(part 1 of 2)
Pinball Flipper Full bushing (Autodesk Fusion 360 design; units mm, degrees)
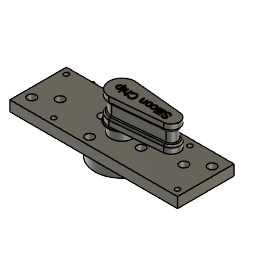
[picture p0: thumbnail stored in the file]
sketch "Flipper" plane through (0, 0, 0) normal (0, 0, 1) x axis (1, 0, 0)
  line L1 (47.7564, -7.9642) -> (0, -12.5)
  line L2 (47.766, 7.9632) -> (1.1968, 12.4426)
  line L3 (-3.0757, 6.1628) -> (6.875, 0.4178)
  line L4 (-6.875, -0.4178) -> (3.0757, -6.1628)
  line L5 (47.7564, 192.0358) -> (0, 187.5)
  line L6 (-6.875, 199.5822) -> (3.0757, 193.8372)
  line L7 (47.766, 207.9632) -> (1.1968, 212.4426)
  line L8 (-3.0757, 206.1628) -> (6.875, 200.4178)
  arc A1 centre (0, 0) radius 12.5 clockwise from (2.3532, -12.2765) to (1.1968, 12.4426)
  arc A2 centre (47, 0) radius 8 clockwise from (47.766, 7.9632) to (47.7564, -7.9642)
  circle C1 centre (0, 0) radius 6.8
  circle C2 centre (3.7239, -2.15) radius 1.4
  circle C3 centre (-3.7239, 2.15) radius 1.4
  arc A3 centre (47, 200) radius 8 clockwise from (47.766, 207.9632) to (47.7564, 192.0358)
  circle C4 centre (-3.7239, 202.15) radius 1.4
  circle C5 centre (0, 200) radius 6.8
  arc A4 centre (0, 200) radius 12.5 clockwise from (2.3532, 187.7235) to (1.1968, 212.4426)
  circle C6 centre (3.7239, 197.85) radius 1.4
  point P1 (0, 0)
  point P2 (0, 0)
  point P4 (0, -12.5)
  point P8 (2.3532, -12.2765)
  point P9 (0, 0)
  point P26 (0, 187.5)
  point P23 (2.3532, 187.7235)
  point P3 (47, 0)
  coincident P1 P2
  coincident P4 A1
  tangent L1 A2
  tangent L2 A1
  tangent L2 A2
  coincident L1 P8
  coincident P1 P9
  coincident P26 A4
  tangent L5 A3
  tangent L7 A4
  tangent A3 L7
  coincident P23 L5
  dimension "d6" diameter C1 = 13.6
  dimension "d174" diameter P3 = 4
  dimension "d363" diameter C2 = 2.8
  dimension "d364" diameter C3 = 2.8
  dimension "d578" diameter C5 = 13.6
  dimension "d579" diameter C6 = 2.8
  dimension "d580" diameter C4 = 2.8
sketch "Bushing" plane through (0, 0, 0) normal (0, 0, 1) x axis (1, 0, 0)
  circle C1 centre (0, 0) radius 7.3
  circle C2 centre (0, 0) radius 11
  circle C3 centre (0, 200) radius 7.3
  circle C4 centre (0, 200) radius 11
  point P1 (0, 0)
  point P2 (0, 0)
  point P3 (0, 0)
  coincident P1 P2
  coincident P1 P3
extrude "Extrude1" new body sketch "Flipper" profile of A1 A2 L1 L2 C1 L4 L3 C2 C3 blind 25 from offset 0.7 bodies "DO NOT USE FLIPPER PROTO"
extrude "Extrude2" add sketch "Flipper" profile of C1 L4 L3 C2 C3 against normal blind 30.8 and along normal blind 0.7
sketch "Washers Upper" plane through (0, 0, 0) normal (0, 0, 1) x axis (1, 0, 0)
  circle C1 centre (0, 0) radius 13.5
  circle C2 centre (0, 0) radius 7.3
  circle C3 centre (0, 200) radius 13.5
  circle C4 centre (0, 200) radius 7.3
  point P1 (0, 0)
  point P2 (0, 0)
  point P3 (0, 0)
  coincident P1 P2
  coincident P1 P3
  dimension "d368" diameter C1 = 27
  dimension "d581" diameter C3 = 27
extrude "Extrude3" new body sketch "Washers Upper" profile of C1 C2 blind -0.8 from offset 0.4 bodies "Washer Upper"
extrude "Extrude4" new body sketch "Bushing" profile of C1 C2 blind -29 from offset -10.2 bodies "Base and Bushing 9mm deck"
sketch "Deck Section" plane through (0, 0, 0) normal (0, 0, 1) x axis (1, 0, 0)
  line L1 (-50, 50) -> (-50, 0)
  line L2 (50, 50) -> (-50, 50)
  line L3 (50, -50) -> (50, 50)
  line L4 (-50, -50) -> (50, -50)
  line L5 (-50, 0) -> (-50, -50)
  circle C1 centre (0, 0) radius 11.5
  point P1 (0, 0)
  point P2 (0, 0)
  coincident P1 P2
  vertical L1
  perpendicular L1 L2
  perpendicular L2 L3
  perpendicular L3 L4
  perpendicular L2 L5
extrude "Extrude5" new body sketch "Deck Section" blind -9 from offset -1.2 bodies "Base Section"
sketch "Solenoid Assembly" plane through (0, 0, -10.2) normal (0, 0, -1) x axis (1, 0, 0)
  line L1 (25, -25) -> (25, 25)
  line L2 (-100, -25) -> (25, -25)
  line L3 (-100, 25) -> (-100, -25)
  line L4 (25, 25) -> (-100, 25)
  line L5 (-100, 225) -> (-100, 175)
  line L6 (25, 175) -> (25, 225)
  line L7 (-100, 175) -> (25, 175)
  line L8 (25, 225) -> (-100, 225)
  circle C1 centre (0, 0) radius 11.5
  circle C2 centre (0, 0) radius 7.3
  circle C3 centre (0, 200) radius 7.3
  point P1 (0, 0)
  point P3 (0, 0)
  coincident P1 P3
  vertical L1
  perpendicular L2 L3
  perpendicular L1 L4
  vertical L6
  perpendicular L5 L7
  perpendicular L6 L8
sketch "Solenoid 22mm" plane through (0, 0, 0) normal (0, 0, 1) x axis (1, 0, 0)
  line L1 (-11, 0) -> (-11, -26)
  line L2 (11, -26) -> (11, 0)
  line L3 (-11, -26) -> (11, -26)
  line L4 (11, 0) -> (-11, 0)
  circle C1 centre (6, -5) radius 1.8
  circle C2 centre (-6, -20) radius 1.8
  point P2 (11, -26)
  point P3 (11, -26)
  point P4 (11, -26)
  coincident P2 P3
  horizontal L3
  perpendicular L1 L3
  perpendicular L1 L4
  coincident P2 P4
  perpendicular L2 L3
sketch "Solenoid 37mm" plane through (0, 0, 0) normal (0, 0, 1) x axis (1, 0, 0)
  line L1 (-2.5, -5.5015) -> (-2.506, -11.3658)
  line L2 (-11, 0) -> (-11, -37)
  line L3 (-5.5, -5.5015) -> (-5.494, -11.3656)
  line L4 (-11, 0) -> (11, 0)
  line L5 (2.5, -31.4995) -> (2.5022, -25.4191)
  line L6 (-2.5, -25.5008) -> (-2.503, -31.4046)
  line L7 (5.5, -25.5) -> (5.5, -31.5)
  line L8 (11, 0) -> (11, -37)
  line L9 (-5.5, -25.5) -> (-5.5, -31.5)
  line L10 (-11, -37) -> (11, -37)
  line L11 (2.5, -5.5015) -> (2.506, -11.3658)
  line L12 (-11, 0) -> (-11, -37)
  line L13 (-11, 0) -> (11, 0)
  line L14 (11, 0) -> (11, -37)
  line L15 (5.5, -5.5015) -> (5.494, -11.3656)
  line L16 (-11, -37) -> (11, -37)
  line L17 (-11, 0) -> (-11, -37)
  line L18 (-11, 0) -> (11, 0)
  line L19 (2.5, -31.4995) -> (2.5021, -25.5799)
  line L20 (5.5, -25.5) -> (5.5, -31.5)
  line L21 (11, 0) -> (11, -37)
  line L22 (-11, -37) -> (11, -37)
  circle C1 centre (4, -28.5) radius 1.5
  arc A1 centre (-4, -31.5) radius 1.5 clockwise from (-2.503, -31.4046) to (-5.5, -31.5)
  arc A2 centre (-4, -25.5) radius 1.5 clockwise from (-5.5, -25.5) to (-2.5, -25.5008)
  arc A3 centre (-4, -11.5) radius 1.5 clockwise from (-2.506, -11.3658) to (-5.494, -11.3656)
  arc A4 centre (4, -11.5) radius 1.5 clockwise from (5.4939, -11.365) to (2.5061, -11.365)
  circle C2 centre (-4, -28.5) radius 1.5
  arc A5 centre (4, -31.5) radius 1.5 clockwise from (5.5, -31.5) to (2.5, -31.4995)
  arc A6 centre (4, -25.5) radius 1.5 clockwise from (2.5022, -25.4191) to (5.5, -25.5)
  arc A7 centre (-4, -5.5) radius 1.5 clockwise from (-5.5, -5.5015) to (-2.5, -5.5015)
  circle C3 centre (-4, -8.5) radius 1.5
  circle C4 centre (4, -8.5) radius 1.5
  circle C5 centre (4, -28.5) radius 1.5
  arc A8 centre (-4, -31.5) radius 1.5 clockwise from (-2.503, -31.4045) to (-5.5, -31.5)
  arc A9 centre (4, -5.5) radius 1.5 clockwise from (2.5, -5.5015) to (5.5, -5.5015)
  arc A10 centre (-4, -11.5) radius 1.5 clockwise from (-2.5061, -11.365) to (-5.4939, -11.365)
  arc A11 centre (4, -11.5) radius 1.5 clockwise from (5.494, -11.3656) to (2.506, -11.3658)
  circle C6 centre (-4, -28.5) radius 1.5
  arc A12 centre (4, -31.5) radius 1.5 clockwise from (5.5, -31.5) to (2.5, -31.4995)
  circle C7 centre (-4, -8.5) radius 1.5
  circle C8 centre (4, -8.5) radius 1.5
  circle C9 centre (4, -28.5) radius 1.5
  arc A13 centre (-4, -31.5) radius 1.5 clockwise from (-2.503, -31.4045) to (-5.5, -31.5)
  arc A14 centre (-4, -11.5) radius 1.5 clockwise from (-2.5061, -11.365) to (-5.4939, -11.365)
  arc A15 centre (4, -11.5) radius 1.5 clockwise from (5.4939, -11.365) to (2.5061, -11.365)
  circle C10 centre (-4, -28.5) radius 1.5
  arc A16 centre (4, -31.5) radius 1.5 clockwise from (5.5, -31.5) to (2.5, -31.4995)
  arc A17 centre (4, -25.5) radius 1.5 clockwise from (2.5021, -25.5799) to (5.5, -25.5)
  circle C11 centre (-4, -8.5) radius 1.5
  circle C12 centre (4, -8.5) radius 1.5
  point P28 (2.5, -31.4995)
  point P7 (2.5, -31.4995)
  point P83 (2.5, -31.4995)
  point P67 (2.5, -31.4995)
  tangent L1 A7
  tangent L3 A7
  tangent A2 L6
  tangent A6 L7
  coincident P28 A5
  tangent A5 L5
  tangent A2 L9
  coincident P7 L5
  tangent A9 L15
  tangent L11 A9
  tangent A17 L20
  coincident P83 A16
  tangent A16 L19
  coincident P67 L19
extrude "Extrude6" new body sketch "Solenoid 22mm" along normal blind 25 bodies "Solenoid 22mm"
extrude "Extrude7" new body sketch "Solenoid 37mm" along normal blind 26 bodies "Solenoid 37mm"
sketch "Solenoid 37mm Plunger" plane through (0, -37, 0) normal (0, -1, 0) x axis (1, 0, 0)
  line L1 (11, 0) -> (-11, 0)
  line L2 (11, 26) -> (11, 0)
  line L3 (-11, 26) -> (11, 26)
  line L4 (-11, 0) -> (-11, 26)
  circle C1 centre (0, 12.5) radius 4
extrude "Extrude8" add sketch "Solenoid 37mm Plunger" profile of C1 along normal blind 23
sketch "Solenoid 22mm Plunger" plane through (0, -26, 0) normal (0, -1, 0) x axis (1, 0, 0)
  line L1 (11, 0) -> (-11, 0)
  line L2 (11, 25) -> (11, 0)
  line L3 (-11, 25) -> (11, 25)
  line L4 (-11, 0) -> (-11, 25)
  circle C1 centre (0, 12.5) radius 4
extrude "Extrude9" add sketch "Solenoid 22mm Plunger" profile of C1 along normal blind 20
sketch "Washer Lower TBA" plane through (0, 0, -10.2) normal (0, 0, -1) x axis (1, 0, 0)
  circle C1 centre (0, 0) radius 15
  circle C2 centre (0, 0) radius 11.5
  circle C3 centre (0, 200) radius 15
  circle C4 centre (0, 200) radius 11.5
  dimension "d38" diameter C1 = 30
  dimension "d582" diameter C3 = 30
move_face "MoveFace1"
extrude "Extrude11" cut sketch "Flipper" profile of C1 L4 L3 blind -19 taper 3 from offset -22.3
sketch "Flipper Drive" plane through (0, 0, -10.2) normal (0, 0, -1) x axis (1, 0, 0)
  line L1 (-0.123, 7.0989) -> (-6.7129, -2.3124)
  line L2 (6.7129, 2.3124) -> (0.123, -7.0989)
  line L3 (-12.2873, 8.6036) -> (0, 0)
  line L4 (-3.5311, 12.3916) -> (-8.1915, 5.7358)
  line L5 (9.4727, 26.0261) -> (0, 0)
  line L6 (25.5365, 11.9079) -> (0, 0)
  line L7 (-11.1615, -30.666) -> (0, 0)
  line L8 (30.0891, 14.0308) -> (0, 0)
  line L9 (-3.473, 19.6962) -> (0, 0)
  line L10 (23.9139, 11.1513) -> (0, 0)
  line L11 (-12.8558, 15.3209) -> (0, 0)
  line L12 (25.7028, 11.9854) -> (0, 0)
  line L13 (0, 0) -> (3.473, -19.6962)
  line L14 (0, 0) -> (12.8558, -15.3209)
  line L15 (25.4979, -9.2805) -> (0, 0)
  line L16 (24.592, 11.4674) -> (0, 0)
  line L17 (0, 0) -> (-25.4979, 9.2805)
  line L18 (23.8505, 4.2055) -> (0, 0)
  line L19 (21.9493, 10.2351) -> (0, 0)
  line L20 (0, 0) -> (-24.5999, 0)
  line L21 (19.205, 16.1149) -> (0, 0)
  line L22 (21.4291, 9.9926) -> (0, 0)
  line L23 (0, 0) -> (-15.3639, -18.31)
  line L24 (-20.1737, -24.0421) -> (0, 0)
  line L25 (28.4442, 13.2638) -> (0, 0)
  line L26 (-28.4796, 0) -> (0, 0)
  line L27 (25.8113, 12.036) -> (0, 0)
  line L28 (30.112, 5.3096) -> (23.8505, 4.2055)
  line L29 (25.0112, 20.9869) -> (19.205, 16.1149)
  line L30 (2.8887, 206.4858) -> (-7.0612, 200.7412)
  line L31 (0, 200) -> (5.1764, 180.6815)
  line L32 (29.5346, 192.0862) -> (23.3932, 193.7318)
  line L33 (28.4796, 200) -> (0, 200)
  line L34 (-23.0757, 176.9243) -> (0, 200)
  line L35 (26.3861, 200) -> (0, 200)
  line L36 (33.1997, 200) -> (0, 200)
  line L37 (31.5373, 208.4504) -> (24.2161, 206.4887)
  line L38 (27.1343, 200) -> (0, 200)
  line L39 (24.2184, 200) -> (0, 200)
  line L40 (-7.5, 212.9904) -> (0, 200)
  line L41 (7.0612, 199.2588) -> (-2.8887, 193.5142)
  line L42 (0, 200) -> (-5.1764, 180.6815)
  line L43 (23.6444, 200) -> (0, 200)
  line L44 (0, 200) -> (-21.6626, 189.8986)
  line L45 (-28.4442, 186.7362) -> (0, 200)
  line L46 (0, 200) -> (-22.295, 210.3963)
  line L47 (19.5843, 219.5843) -> (0, 200)
  line L48 (0, 200) -> (-19.1868, 219.1868)
  line L49 (24.2161, 206.4887) -> (0, 200)
  line L50 (28.1764, 200) -> (0, 200)
  line L51 (-25.8113, 212.036) -> (0, 200)
  line L52 (23.3932, 193.7318) -> (0, 200)
  line L53 (28.3599, 200) -> (0, 200)
  line L54 (-5.1764, 219.3185) -> (0, 200)
  line L55 (2.0367, 212.7229) -> (-5, 208.6603)
  line L56 (5.1764, 219.3185) -> (0, 200)
  line L57 (19.1868, 180.8132) -> (0, 200)
  line L58 (31.3847, 200) -> (0, 200)
  line L59 (14.274, 17.0132) -> (0, 0)
  line L60 (22.8697, 27.2586) -> (14.274, 17.0132)
  line L61 (22.194, 0.0202) -> (0, 0)
  line L62 (30.71, 0.0279) -> (22.194, 0.0202)
  line L63 (-0.123, 7.0989) -> (-6.7129, -2.3124)
  line L64 (6.7129, 2.3124) -> (0.123, -7.0989)
  line L65 (2.8887, 6.4858) -> (-7.0612, 0.7412)
  line L66 (7.0612, -0.7412) -> (-2.8887, -6.4858)
  arc A1 centre (0, 0) radius 7.1 clockwise from (0.123, -7.0989) to (-6.7129, -2.3124)
  arc A2 centre (0, 0) radius 7.1 clockwise from (-0.123, 7.0989) to (6.7129, 2.3124)
  circle C1 centre (0, 0) radius 15
  arc A3 centre (0, 0) radius 7.1 clockwise from (-6.7129, -2.3124) to (-0.123, 7.0989)
  arc A4 centre (0, 0) radius 7.1 clockwise from (6.7129, 2.3124) to (0.123, -7.0989)
  arc A5 centre (0, 0) radius 20 clockwise from (-12.8558, 15.3209) to (-3.473, 19.6962)
  arc A6 centre (0, 0) radius 20 clockwise from (12.8558, -15.3209) to (3.473, -19.6962)
  arc A7 centre (0, 0) radius 16 clockwise from (5.4723, 15.0351) to (12.2567, 10.2846)
  arc A8 centre (0, 0) radius 16 clockwise from (15.7569, 2.7784) to (15.0351, -5.4723)
  arc A9 centre (0, 0) radius 16 clockwise from (-5.4723, -15.0351) to (-10.2846, -12.2567)
  arc A10 centre (0, 0) radius 16 clockwise from (-16, 0) to (-15.0351, 5.4723)
  arc A11 centre (0, 0) radius 16 clockwise from (12.2567, 10.2846) to (15.7569, 2.7784)
  arc A12 centre (0, 0) radius 16 clockwise from (-10.2846, -12.2567) to (-16, 0)
  arc A13 centre (0, 0) radius 21 clockwise from (-13.4985, -16.0869) to (-21, 0)
  arc A14 centre (0, 0) radius 26 clockwise from (8.8925, 24.432) to (24.432, -8.8925)
  arc A15 centre (0, 0) radius 26 clockwise from (-8.8925, -24.432) to (-16.7125, -19.9172)
  arc A16 centre (0, 0) radius 26 clockwise from (-26, 0) to (-24.432, 8.8925)
  arc A17 centre (0, 0) radius 26 clockwise from (24.432, -8.8925) to (-8.8925, -24.432)
  arc A18 centre (0, 0) radius 21 clockwise from (-19.7335, 7.1824) to (7.1824, 19.7335)
  arc A19 centre (0, 0) radius 26 clockwise from (-24.432, 8.8925) to (8.8925, 24.432)
  arc A20 centre (0, 0) radius 21 clockwise from (19.7335, -7.1824) to (-7.1824, -19.7335)
  circle C2 centre (-11.3357, -19.6167) radius 1.75
  circle C3 centre (-11.3357, -19.6167) radius 4
  circle C4 centre (-22.3238, 3.9473) radius 1.75
  circle C5 centre (-22.3238, 3.9473) radius 4
  circle C6 centre (11.2096, 19.5842) radius 1.75
  circle C7 centre (11.2096, 19.5842) radius 4
  circle C8 centre (22.1977, -3.9798) radius 1.75
  circle C9 centre (22.1977, -3.9798) radius 4
  arc A21 centre (0, 0) radius 26 clockwise from (-16.7125, -19.9172) to (-26, 0)
  arc A22 centre (0, 200) radius 20 clockwise from (5.1764, 180.6815) to (-5.1764, 180.6815)
  arc A23 centre (0, 200) radius 26 clockwise from (18.3848, 218.3848) to (18.3848, 181.6152)
  circle C10 centre (18.436, 187.0119) radius 4
  arc A24 centre (0, 200) radius 26 clockwise from (-18.3848, 218.3848) to (18.3848, 218.3848)
  arc A25 centre (0, 200) radius 26 clockwise from (18.3848, 181.6152) to (-18.3848, 181.6152)
  arc A26 centre (0, 200) radius 21 clockwise from (-14.8492, 214.8492) to (14.8492, 214.8492)
  circle C11 centre (0, 200) radius 15
  arc A27 centre (0, 200) radius 16 clockwise from (15.4548, 195.8589) to (11.3137, 188.6863)
  arc A28 centre (0, 200) radius 16 clockwise from (-14.5009, 206.7619) to (-11.3137, 211.3137)
  arc A29 centre (0, 200) radius 16 clockwise from (-11.3137, 188.6863) to (-14.5009, 193.2381)
  arc A30 centre (0, 200) radius 16 clockwise from (15.4548, 204.1411) to (15.4548, 195.8589)
  arc A31 centre (0, 200) radius 21 clockwise from (14.8492, 185.1508) to (-14.8492, 185.1508)
  circle C12 centre (18.436, 213.0119) radius 4
  circle C13 centre (18.436, 213.0119) radius 1.75
  arc A32 centre (0, 200) radius 26 clockwise from (-18.3848, 181.6152) to (-23.564, 189.0119)
  arc A33 centre (0, 200) radius 26 clockwise from (-23.564, 210.9881) to (-18.3848, 218.3848)
  circle C14 centre (-18.564, 187.0119) radius 1.75
  circle C15 centre (-18.564, 187.0119) radius 4
  arc A34 centre (0, 200) radius 7.1 clockwise from (-7.0612, 200.7412) to (2.8887, 206.4858)
  circle C16 centre (-18.564, 213.0119) radius 4
  arc A35 centre (0, 200) radius 7.1 clockwise from (7.0612, 199.2588) to (-2.8887, 193.5142)
  arc A36 centre (0, 200) radius 16 clockwise from (-14.5009, 193.2381) to (-14.5009, 206.7619)
  circle C17 centre (-18.564, 213.0119) radius 1.75
  arc A37 centre (0, 200) radius 7.1 clockwise from (-2.8887, 193.5142) to (-7.0612, 200.7412)
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  point P1 (0, 0)
  point P2 (0, 0)
  point P3 (6.7129, 2.3124)
  point P8 (0, 0)
  point P12 (-12.2873, 8.6036)
  point P7 (0, 0)
  point P15 (0, 0)
  point P14 (0, 0)
  point P18 (0, 0)
  point P11 (0, 0)
  point P21 (0, 0)
  point P23 (0, 0)
  point P26 (0, 0)
  point P27 (0, 0)
  point P30 (0, 0)
  point P33 (0, 0)
  point P38 (0, 0)
  point P43 (0, 0)
  point P49 (12.2567, 10.2846)
  point P50 (5.4723, 15.0351)
  point P48 (0, 0)
  point P53 (15.7569, 2.7784)
  point P36 (0, 0)
  point P51 (0, 0)
  point P55 (-10.2846, -12.2567)
  point P54 (0, 0)
  point P57 (-13.4985, -16.0869)
  point P58 (-21, 0)
  point P61 (-16, 0)
  point P60 (-15.0351, 5.4723)
  point P59 (0, 0)
  point P62 (0, 0)
  point P46 (-15.3639, -18.31)
  point P65 (0, 0)
  point P41 (-24.5999, 0)
  point P68 (0, 0)
  point P13 (0, 0)
  point P71 (0, 0)
  point P75 (8.8925, 24.432)
  point P77 (-16.7125, -19.9172)
  point P76 (0, 0)
  point P81 (-26, 0)
  point P79 (0, 0)
  point P82 (0, 0)
  point P85 (-19.7335, 7.1824)
  point P83 (0, 0)
  point P86 (0, 0)
  point P88 (-7.1824, -19.7335)
  point P73 (0, 0)
  point P87 (0, 0)
  point P42 (0, 0)
  point P98 (0, 0)
  point P129 (7.0612, 199.2588)
  point P128 (0, 200)
  point P135 (0, 200)
  point P117 (-7.5, 212.9904)
  point P133 (0, 200)
  point P137 (0, 200)
  point P112 (0, 200)
  point P140 (0, 200)
  point P118 (0, 200)
  point P155 (0, 200)
  point P171 (0, 200)
  point P177 (0, 200)
  point P178 (0, 200)
  point P182 (0, 200)
  point P174 (0, 200)
  point P125 (0, 200)
  point P163 (0, 200)
  point P161 (15.4548, 204.1411)
  point P162 (11.3137, 211.3137)
  point P166 (0, 200)
  point P151 (15.4548, 195.8589)
  point P153 (0, 200)
  point P183 (0, 200)
  point P194 (-14.5009, 193.2381)
  point P191 (-19.0325, 191.125)
  point P192 (-19.0325, 208.875)
  point P176 (-14.5009, 206.7619)
  point P175 (-11.3137, 211.3137)
  point P193 (0, 200)
  point P165 (-21.6626, 189.8986)
  point P185 (0, 200)
  point P168 (-22.295, 210.3963)
  point P109 (0, 200)
  point P113 (0, 200)
  point P121 (0, 200)
  point P105 (18.3848, 218.3848)
  point P144 (-23.564, 189.0119)
  point P99 (0, 200)
  point P148 (-23.564, 210.9881)
  point P147 (0, 200)
  point P190 (0, 200)
  point P149 (0, 200)
  point P146 (-14.8492, 214.8492)
  point P143 (0, 200)
  point P106 (0, 200)
  point P123 (-14.8492, 185.1508)
  point P111 (0, 200)
  point P124 (0, 200)
  point P110 (0, 200)
  point P157 (0, 200)
  point P196 (0, 0)
  point P197 (20.9994, -0.1635)
  point P198 (13.3537, 16.2074)
  point P199 (0, 0)
  point P200 (14.274, 17.0132)
  point P202 (0, 0)
  point P203 (22.194, 0.0202)
  point P205 (0, 0)
  point P207 (-18.7939, 6.8404)
  point P206 (0, 0)
  point P209 (18.7939, -6.8404)
  point P208 (0, 0)
  coincident P1 P2
  coincident P3 A1
  coincident P2 P8
  concentric A1 C1
  coincident C1 P12
  coincident P7 P15
  coincident P14 P18
  coincident P11 P21
  coincident P2 P23
  coincident P26 P27
  coincident P27 P30
  coincident P7 P33
  coincident P11 P38
  coincident P2 P43
  coincident L21 P49
  coincident L5 P50
  coincident P14 P48
  coincident L18 P53
  coincident P36 P51
  coincident L23 P55
  coincident P1 P54
  coincident L23 P57
  coincident L20 P58
  coincident L20 P61
  coincident L17 P60
  coincident P27 P59
  coincident P1 P62
  coincident P46 L24
  parallel L23 L24
  coincident P7 P65
  coincident P41 L26
  parallel L20 L26
  coincident P51 P68
  parallel L18 L28
  parallel L21 L29
  coincident P13 P71
  coincident L5 P75
  coincident L24 P77
  coincident P13 P76
  coincident L26 P81
  coincident P54 P79
  coincident P54 P82
  coincident L17 P85
  coincident P82 P83
  coincident P59 P86
  coincident L7 P88
  coincident P73 P87
  concentric C2 C3
  concentric C4 C5
  concentric C8 C9
  concentric C6 C7
  coincident P42 P98
  coincident P129 A37
  coincident P128 P135
  concentric C11 A37
  coincident P117 C11
  horizontal L50
  coincident P133 P137
  horizontal L36
  coincident P112 P140
  horizontal L35
  coincident P118 P155
  horizontal L53
  coincident P128 P171
  coincident P177 P178
  coincident P177 P182
  horizontal L38
  coincident P133 P174
  horizontal L39
  coincident P118 P125
  horizontal L43
  coincident P128 P163
  coincident P161 L49
  coincident P162 L47
  coincident P112 P166
  coincident P151 L52
  coincident P153 P183
  coincident P194 L44
  coincident P191 L44
  coincident P192 L46
  coincident P176 L46
  coincident P175 L48
  coincident P177 P193
  horizontal L58
  coincident P165 L45
  parallel L44 L45
  horizontal L33
  coincident P133 P185
  coincident P168 L51
  parallel L46 L51
  coincident P109 P153
  parallel L32 L52
  parallel L37 L49
  coincident P113 P121
  coincident P105 L47
  coincident P144 L45
  coincident P99 P113
  coincident P148 L51
  coincident P147 P190
  coincident P149 P190
  coincident P146 L48
  coincident P143 P149
  coincident P106 P193
  coincident P123 L34
  coincident P111 P124
  concentric C14 C15
  concentric C16 C17
  concentric C12 C13
  coincident P110 P157
  coincident P14 P196
  coincident C9 P197
  coincident C7 P198
  coincident P11 P199
  coincident C7 P200
  tangent C7 L59
  tangent C7 L60
  coincident P76 P202
  coincident C9 P203
  tangent C9 L61
  tangent C9 L62
  coincident P59 P205
  coincident L17 P207
  coincident P54 P206
  coincident L15 P209
  coincident P14 P208
  dimension "d299" angle L7 L8 = 135
  dimension "d300" angle L9 L10 = 75
  dimension "d301" angle L11 L12 = 105
  dimension "d302" radius A5 = 20
  dimension "d303" radius A6 = 20
  dimension "d307" radius A7 = 16
  dimension "d309" radius A8 = 16
  dimension "d311" radius A9 = 16
  dimension "d314" radius A10 = 16
  dimension "d513" radius A14 = 26
  dimension "d514" radius A15 = 26
  dimension "d515" radius A16 = 26
  dimension "d517" radius A18 = 21
  dimension "d518" radius A20 = 21
  dimension "d520" diameter C2 = 3.5
  dimension "d521" diameter C3 = 8
  dimension "d522" diameter C4 = 3.5
  dimension "d523" diameter C5 = 8
  dimension "d524" diameter C8 = 3.5
  dimension "d525" diameter C9 = 8
  dimension "d526" diameter C6 = 3.5
  dimension "d527" diameter C7 = 8
  dimension "d583" angle L34 L36 = 135
  dimension "d584" angle L35 L56 = 75
  dimension "d585" angle L53 L54 = 105
  dimension "d586" radius = 20
  dimension "d587" radius A22 = 20
  dimension "d588" radius = 16
  dimension "d589" radius A27 = 16
  dimension "d590" radius A29 = 16
  dimension "d591" radius A28 = 16
  dimension "d592" radius A23 = 26
  dimension "d593" radius A32 = 26
  dimension "d594" radius A33 = 26
  dimension "d595" radius A26 = 21
  dimension "d596" radius A31 = 21
  dimension "d597" diameter C14 = 3.5
  dimension "d598" diameter C15 = 8
  dimension "d599" diameter C17 = 3.5
  dimension "d600" diameter C16 = 8
  dimension "d601" diameter = 3.5
  dimension "d602" diameter C10 = 8
  dimension "d603" diameter C13 = 3.5
  dimension "d604" diameter C12 = 8
  dimension "d730" radius = 21
work_plane "WorkPlane1" RotateAngle 90
sketch "Flipper Drive Perpendicular Plane" plane through (0, 0, 0) normal (-0.5736, 0.8192, 0) x axis (-0.8192, -0.5736, 0)
  circle C1 centre (10, -32.2) radius 2
  circle C2 centre (10, -32.2) radius 4.5
  circle C3 centre (-10, -32.2) radius 2
  circle C4 centre (-10, -32.2) radius 4.5
  dimension "d51" diameter C1 = 4
  dimension "d52" diameter C2 = 9
  dimension "d53" diameter C3 = 4
  dimension "d54" diameter C4 = 9
extrude "Extrude12" new body sketch "Flipper Drive" profile of A2 C1 A3 A4 blind 8.8 from offset 11.2 bodies "Flipper Drive"
extrude "Extrude13" add sketch "Flipper Drive" profile of L1 L2 L3 A3 A4 blind 8.8 taper 3 from offset 11.2
sketch "Flipper Drive Top Labelling" plane through (0, 0, -30.2) normal (0, 0, -1) x axis (1, 0, 0)
  line L1 (3.3862, 6.2405) -> (-7.0975, 0.1877)
  line L2 (-3.3862, -6.2405) -> (7.0975, -0.1877)
  curve K1
  curve K2
  curve K3
  curve K4
  curve K5
  curve K6
  curve K7
  curve K8
  line L3 (10, 0) -> (0, 0)
  line L4 (0.4316, 7.0869) -> (-6.5119, -2.8294)
  line L5 (-0.4316, -7.0869) -> (6.5119, 2.8294)
  arc A1 centre (0, 0) radius 7.1 clockwise from (-3.3862, -6.2405) to (-7.0975, 0.1877)
  circle C1 centre (-5, 8.6603) radius 5
  circle C2 centre (-5, 8.6603) radius 3
  circle C3 centre (-5, 8.6603) radius 1.75
  arc A2 centre (0, 0) radius 7.1 clockwise from (3.3862, 6.2405) to (7.0975, -0.1877)
  circle C4 centre (0, 0) radius 15
  arc A3 centre (0, 0) radius 7.1 clockwise from (-0.4316, -7.0869) to (-6.5119, -2.8294)
  arc A4 centre (0, 0) radius 7.1 clockwise from (0.4316, 7.0869) to (6.5119, 2.8294)
  circle C5 centre (0, 0) radius 15
  circle C6 centre (5, -8.6603) radius 1.75
  circle C7 centre (5, -8.6603) radius 3
  circle C8 centre (5, -8.6603) radius 5
  point P1 (0, 0)
  point P8 (0, 0)
  horizontal L3
  coincident P1 P8
  concentric C1 C2
  concentric C1 C3
  concentric C7 C8
  concentric C6 C8
  dimension "d75" Text1-Height = 5
  dimension "d77" Text2-Height = 3
extrude "Extrude20" cut sketch "Flipper Drive Top Labelling" against normal blind 0.6
sketch "Flipper Drive Lower Assembly" plane through (0, 0, -10.2) normal (0, 0, -1) x axis (1, 0, 0)
  line L1 (40.6874, -6.549) -> (14.7287, 38.4892)
  line L2 (-113.7703, -35.5739) -> (14.7287, 38.4892)
  line L3 (-87.8117, -80.6121) -> (12.9793, -22.5191)
  line L4 (40.6874, -6.549) -> (12.9793, -22.5191)
  line L5 (-87.8117, -80.6121) -> (-113.7703, -35.5739)
  line L6 (20.7934, 41.9847) -> (14.7287, 38.4892)
  line L7 (46.7521, -3.0534) -> (40.6874, -6.549)
  line L8 (-94.1551, -30.9647) -> (-102.8153, -35.9647)
  line L9 (-83.4756, -35.9647) -> (-102.8153, -35.9647)
  line L10 (-90.691, -28.9647) -> (-94.1551, -30.9647)
  line L11 (19.0606, 40.986) -> (14.7287, 38.4892)
  circle C1 centre (0, 0) radius 11
  circle C2 centre (-82.8153, -70.6057) radius 2.25
  circle C3 centre (-102.8153, -35.9647) radius 2.25
  circle C4 centre (12.3745, 30.5207) radius 2.25
  circle C5 centre (32.3745, -4.1204) radius 2.25
  point P1 (0, 0)
  point P2 (0, 0)
  point P9 (-102.8153, -35.9647)
  point P14 (-102.8153, -35.9647)
  point P15 (-94.1551, -30.9647)
  point P17 (-90.691, -28.9647)
  point P3 (14.7287, 38.4892)
  point P18 (19.0606, 40.986)
  coincident P1 P2
  perpendicular L1 L2
  perpendicular L1 L4
  perpendicular L3 L5
  perpendicular L1 L6
  perpendicular L1 L7
  horizontal L9
  coincident P9 P14
  parallel L8 L10
  perpendicular L1 L11
  dimension "d132" diameter C2 = 4.5
  dimension "d135" diameter C3 = 4.5
  dimension "d138" diameter C4 = 4.5
  dimension "d139" diameter C5 = 4.5
  dimension "d348" angle L8 L9 = 30
  dimension "d349" distance P14 P15 = 10
  dimension "d357" distance P15 P17 = 4
  dimension "d534" distance P3 P18 = 5
extrude "Extrude21" add sketch "Flipper Drive Lower Assembly" profile of C1 L1 L2 L3 L4 L5 along normal blind 10
sketch "Washer Lower" plane through (0, 0, -20.2) normal (0, 0, -1) x axis (1, 0, 0)
  circle C1 centre (0, 0) radius 7.3
  circle C2 centre (0, 0) radius 7.3
  circle C3 centre (0, 0) radius 13.5
  circle C4 centre (0, 200) radius 13.5
  circle C5 centre (0, 200) radius 7.3
  point P1 (0, 0)
  point P3 (0, 0)
  coincident P1 P3
  dimension "d369" diameter C3 = 27
  dimension "d605" diameter C4 = 27
extrude "Extrude22" new body sketch "Washer Lower" profile of C1 C2 C3 blind 1 from offset 0.2 bodies "Washer Lower"
move "Move1"
move "Move2"
move "Move3"
move "Move4"
work_plane "WorkPlane2" RotateAngle 0
sketch "Construction to Solenoid" plane through (0, 0, -32.2) normal (0, 0, 1) x axis (1, 0, 0)
  line L1 (-83.0796, 37.5009) -> (-8.1915, -5.7358)
  line L2 (85.6995, -5.7358) -> (-8.1915, -5.7358)
  point P2 (-8.1915, -5.7358)
  point P3 (-8.1915, -5.7358)
  horizontal L2
  coincident P2 P3
  dimension "d87" angle L1 L2 = 150
move "Move5"
work_axis "WorkAxis2"
move "Move6"
move "Move7"
work_plane "WorkPlane3" AlongDistance 12.5
work_plane "WorkPlane4" RotateAngle 0
work_plane "WorkPlane5" RotateAngle 0
sketch "Solenoid Coupling" plane through (0, 0, -32.2) normal (0, 0, 1) x axis (1, 0, 0)
  line L1 (14.8548, -15.2705) -> (9.7533, -24.1063)
  line L2 (30.5284, -24.3335) -> (14.8548, -15.2705)
  line L3 (25.433, -33.159) -> (30.5284, -24.3335)
  line L4 (25.433, -33.159) -> (9.7533, -24.1063)
  line L5 (47.3229, -34.0286) -> (34.864, -26.8366)
  line L6 (30.5284, -24.3335) -> (34.864, -26.8366)
  line L7 (34.864, -26.8366) -> (30.629, -34.173)
  line L8 (13.6506, -26.3564) -> (16.6506, -21.1603)
  line L9 (22.6506, -21.1603) -> (16.6506, -21.1603)
  line L10 (13.6506, -26.3564) -> (16.6506, -21.1603)
  line L11 (51.0602, -47.9614) -> (53.55, -46.5429)
  line L12 (51.0602, -47.9614) -> (42.896, -43.2346)
  line L13 (-25.136, -26.8366) -> (-29.3244, -34.0923)
  line L14 (-45.1452, -15.2705) -> (-50.2467, -24.1063)
  line L15 (-34.567, -33.159) -> (-29.4716, -24.3335)
  line L16 (-46.3494, -26.3564) -> (-43.3494, -21.1603)
  line L17 (-8.2143, -48.5931) -> (-5.4963, -46.9921)
  line L18 (-11.811, -34.5286) -> (-25.136, -26.8366)
  line L19 (-29.4716, -24.3335) -> (-25.136, -26.8366)
  line L20 (-29.4716, -24.3335) -> (-45.1452, -15.2705)
  line L21 (-37.3494, -21.1603) -> (-43.3494, -21.1603)
  line L22 (-46.3494, -26.3564) -> (-43.3494, -21.1603)
  line L23 (-10.945, -35.0285) -> (-11.811, -34.5286)
  line L24 (-15.3719, -42.1478) -> (-16.2379, -41.6478)
  line L25 (-89.4716, -24.3335) -> (-105.1452, -15.2705)
  line L26 (-97.3494, -21.1603) -> (-103.3494, -21.1603)
  line L27 (-67.4648, -48.7967) -> (-64.8096, -47.2494)
  line L28 (-106.3494, -26.3564) -> (-103.3494, -21.1603)
  line L29 (-106.3494, -26.3564) -> (-103.3494, -21.1603)
  line L30 (-69.7504, -35.7181) -> (-70.6165, -35.2181)
  line L31 (-70.6165, -35.2181) -> (-85.136, -26.8366)
  line L32 (-74.5059, -42.6477) -> (-75.3719, -42.1477)
  line L33 (-85.136, -26.8366) -> (-89.3244, -34.0922)
  line L34 (-67.4648, -48.7967) -> (-75.3719, -44.2345)
  line L35 (-89.4716, -24.3335) -> (-85.136, -26.8366)
  line L36 (-94.567, -33.159) -> (-89.4716, -24.3335)
  line L37 (-105.1452, -15.2705) -> (-110.2467, -24.1063)
  line L38 (-94.567, -33.159) -> (-110.2467, -24.1063)
  line L39 (-156.3494, -26.3564) -> (-153.3494, -21.1603)
  line L40 (-155.1452, -15.2705) -> (-160.2467, -24.1063)
  line L41 (-147.3494, -21.1603) -> (-153.3494, -21.1603)
  line L42 (-119.2129, -36.0285) -> (-120.0789, -35.5285)
  line L43 (-116.307, -49.4732) -> (-113.7939, -48.0094)
  line L44 (-156.3494, -26.3564) -> (-153.3494, -21.1603)
  line L45 (-144.567, -33.159) -> (-139.4716, -24.3335)
  line L46 (-134.27, -27.3366) -> (-138.4584, -34.5922)
  line L47 (-144.567, -33.159) -> (-160.2467, -24.1063)
  line L48 (-139.4716, -24.3335) -> (-134.27, -27.3366)
  line L49 (-139.4716, -24.3335) -> (-155.1452, -15.2705)
  line L50 (-120.0789, -35.5285) -> (-134.27, -27.3366)
  line L51 (-123.6398, -43.1477) -> (-124.5059, -42.6477)
  line L52 (-116.307, -49.4732) -> (-124.5058, -44.7345)
  line L53 (-204.567, -33.159) -> (-220.2467, -24.1063)
  line L54 (-182.7738, -43.6477) -> (-183.6398, -43.1477)
  line L55 (-207.3494, -21.1603) -> (-213.3494, -21.1603)
  line L56 (-215.1452, -15.2705) -> (-220.2467, -24.1063)
  line L57 (-216.3494, -26.3564) -> (-213.3494, -21.1603)
  line L58 (-216.3494, -26.3564) -> (-213.3494, -21.1603)
  line L59 (-199.4716, -24.3335) -> (-215.1452, -15.2705)
  line L60 (-199.4716, -24.3335) -> (-193.404, -27.8366)
  line L61 (-178.3469, -36.5285) -> (-179.2129, -36.0285)
  line L62 (-179.2129, -36.0285) -> (-193.404, -27.8366)
  line L63 (-175.4401, -49.9688) -> (-183.6398, -45.2345)
  line L64 (-204.567, -33.159) -> (-199.4716, -24.3335)
  line L65 (-175.4401, -49.9688) -> (-172.9348, -48.5134)
  line L66 (-193.404, -27.8366) -> (-197.5924, -35.0922)
  line L67 (-264.567, -33.159) -> (-280.2467, -24.1063)
  line L68 (-275.1452, -15.2705) -> (-280.2467, -24.1063)
  line L69 (-234.5746, -50.467) -> (-232.0726, -49.0156)
  line L70 (-238.3469, -36.5285) -> (-252.538, -28.3366)
  line L71 (-259.4716, -24.3335) -> (-252.538, -28.3366)
  line L72 (-252.538, -28.3366) -> (-256.7263, -35.5922)
  line L73 (-234.5746, -50.467) -> (-242.7738, -45.7345)
  line L74 (-259.4716, -24.3335) -> (-275.1452, -15.2705)
  line L75 (-267.3494, -21.1603) -> (-273.3494, -21.1603)
  line L76 (-276.3494, -26.3564) -> (-273.3494, -21.1603)
  line L77 (-276.3494, -26.3564) -> (-273.3494, -21.1603)
  line L78 (-264.567, -33.159) -> (-259.4716, -24.3335)
  line L79 (25.433, -33.159) -> (42.896, -43.2346)
  line L80 (30.629, -34.173) -> (29.7699, -35.6612)
  line L81 (-30.2298, -35.6615) -> (-29.3244, -34.0923)
  line L82 (-90.23, -35.6618) -> (-75.3719, -44.2345)
  line L83 (-90.23, -35.6618) -> (-89.3244, -34.0922)
  line L84 (-90.23, -35.6618) -> (-94.567, -33.159)
  line L85 (-144.567, -33.159) -> (-124.5058, -44.7345)
  line L86 (-139.3638, -36.1613) -> (-138.4584, -34.5922)
  line L87 (-204.567, -33.159) -> (-183.6398, -45.2345)
  line L88 (-198.4977, -36.6611) -> (-197.5924, -35.0922)
  line L89 (-264.567, -33.159) -> (-242.7738, -45.7345)
  line L90 (-257.6316, -37.161) -> (-256.7263, -35.5922)
  line L91 (-326.2039, -23.3339) -> (-319.2703, -27.337)
  line L92 (-331.2993, -32.1594) -> (-346.979, -23.1067)
  line L93 (-343.0816, -25.3568) -> (-340.0816, -20.1607)
  line L94 (-299.5746, -50.467) -> (-297.0726, -49.0156)
  line L95 (-343.0816, -25.3568) -> (-340.0816, -20.1607)
  line L96 (-334.0816, -20.1607) -> (-340.0816, -20.1607)
  line L97 (-326.2039, -23.3339) -> (-341.8775, -14.2709)
  line L98 (-303.3473, -36.5287) -> (-319.2703, -27.337)
  line L99 (-331.2993, -32.1594) -> (-326.2039, -23.3339)
  line L100 (-319.2703, -27.337) -> (-323.4586, -34.5926)
  line L101 (-299.5746, -50.467) -> (-307.7738, -45.7345)
  line L102 (-331.2993, -32.1594) -> (-307.7738, -45.7345)
  line L103 (-341.8775, -14.2709) -> (-346.979, -23.1067)
  line L104 (-324.3639, -36.1614) -> (-323.4586, -34.5926)
  line L105 (-326.0961, -35.1618) -> (-324.3639, -36.1614)
  line L106 (-393.0316, -31.1598) -> (-367.7738, -45.7345)
  line L107 (-381.0025, -26.3374) -> (-385.1909, -33.593)
  line L108 (-386.0961, -35.1618) -> (-385.1909, -33.593)
  line L109 (-393.0316, -31.1598) -> (-408.7112, -22.1071)
  line L110 (-403.6098, -13.2713) -> (-408.7112, -22.1071)
  line L111 (-387.9362, -22.3343) -> (-403.6098, -13.2713)
  line L112 (-395.8139, -19.1611) -> (-401.8139, -19.1611)
  line L113 (-387.9362, -22.3343) -> (-381.0025, -26.3374)
  line L114 (-393.0316, -31.1598) -> (-387.9362, -22.3343)
  line L115 (-359.5746, -50.467) -> (-367.7738, -45.7345)
  line L116 (-404.8139, -24.3572) -> (-401.8139, -19.1611)
  line L117 (-363.3476, -36.5288) -> (-381.0025, -26.3374)
  line L118 (-404.8139, -24.3572) -> (-401.8139, -19.1611)
  line L119 (-359.5746, -50.467) -> (-357.0726, -49.0156)
  line L120 (-387.8284, -34.1622) -> (-386.0961, -35.1618)
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  point P3 (16.6506, -21.1603)
  point P13 (16.6506, -21.1603)
  point P16 (13.6506, -26.3564)
  point P22 (-43.3494, -21.1603)
  point P33 (-43.3494, -21.1603)
  point P35 (-46.3494, -26.3564)
  point P48 (-103.3494, -21.1603)
  point P55 (-103.3494, -21.1603)
  point P47 (-106.3494, -26.3564)
  point P67 (-153.3494, -21.1603)
  point P78 (-153.3494, -21.1603)
  point P65 (-156.3494, -26.3564)
  point P92 (-213.3494, -21.1603)
  point P94 (-213.3494, -21.1603)
  point P93 (-216.3494, -26.3564)
  point P111 (-273.3494, -21.1603)
  point P115 (-273.3494, -21.1603)
  point P112 (-276.3494, -26.3564)
  point P127 (29.7699, -35.6612)
  point P130 (-139.3638, -36.1613)
  point P131 (-198.4977, -36.6611)
  point P132 (-257.6316, -37.161)
  point P138 (-340.0816, -20.1607)
  point P139 (-340.0816, -20.1607)
  point P136 (-343.0816, -25.3568)
  point P133 (-324.3639, -36.1614)
  point P155 (-401.8139, -19.1611)
  point P161 (-401.8139, -19.1611)
  point P159 (-404.8139, -24.3572)
  point P158 (-386.0961, -35.1618)
  point P181 (138.3827, -22.1603)
  point P202 (138.3827, -22.1603)
  point P201 (77.5167, -21.6603)
  point P220 (77.5167, -21.6603)
  point P14 (13.6506, -26.3564)
  point P34 (-46.3494, -26.3564)
  point P30 (-11.811, -34.5286)
  point P40 (-10.945, -35.0285)
  point P28 (-16.2379, -41.6478)
  point P41 (-15.3719, -42.1478)
  point P46 (-106.3494, -26.3564)
  point P49 (-69.7504, -35.7181)
  point P61 (-70.6165, -35.2181)
  point P51 (-74.5059, -42.6477)
  point P54 (-75.3719, -42.1477)
  point P74 (-156.3494, -26.3564)
  point P72 (-119.2129, -36.0285)
  point P83 (-120.0789, -35.5285)
  point P75 (-123.6398, -43.1477)
  point P77 (-124.5059, -42.6477)
  point P98 (-216.3494, -26.3564)
  point P91 (-178.3469, -36.5285)
  point P105 (-179.2129, -36.0285)
  point P99 (-182.7738, -43.6477)
  point P101 (-183.6398, -43.1477)
  point P124 (-276.3494, -26.3564)
  point P146 (-343.0816, -25.3568)
  point P153 (-326.0961, -35.1618)
  point P167 (-404.8139, -24.3572)
  point P154 (-387.8284, -34.1622)
  point P203 (135.3827, -27.3564)
  point P208 (74.5167, -26.8564)
  point P210 (109.055, -35.0285)
  point P213 (108.189, -34.5286)
  point P214 (104.6281, -42.1478)
  point P219 (103.7621, -41.6478)
  point P197 (75.7208, -15.7705)
  point P229 (76.5868, -16.2705)
  point P186 (136.5868, -16.2705)
  point P230 (138.3189, -17.2706)
  perpendicular L3 L4
  perpendicular L3 L6
  perpendicular L5 L7
  horizontal L9
  coincident P3 P13
  perpendicular L4 L8
  coincident L8 P16
  coincident L4 P16
  perpendicular L15 L19
  perpendicular L13 L18
  horizontal L21
  coincident P22 P33
  coincident P35 L22
  parallel L18 L23
  perpendicular L36 L38
  perpendicular L35 L36
  perpendicular L31 L33
  horizontal L26
  coincident P48 P55
  perpendicular L28 L38
  coincident P47 L28
  coincident P47 L38
  parallel L30 L31
  perpendicular L45 L47
  perpendicular L45 L48
  perpendicular L46 L50
  horizontal L41
  coincident P67 P78
  perpendicular L39 L47
  coincident P65 L39
  coincident P65 L47
  parallel L42 L50
  perpendicular L53 L64
  perpendicular L60 L64
  perpendicular L62 L66
  horizontal L55
  coincident P92 P94
  perpendicular L53 L57
  coincident P93 L57
  coincident P93 L53
  parallel L61 L62
  perpendicular L67 L78
  perpendicular L71 L78
  perpendicular L70 L72
  horizontal L75
  coincident P111 P115
  perpendicular L67 L77
  coincident P112 L77
  coincident P112 L67
  coincident L79 P127
  parallel L7 L80
  parallel L34 L82
  perpendicular L82 L83
  coincident L85 P130
  perpendicular L85 L86
  coincident L87 P131
  perpendicular L87 L88
  coincident L89 P132
  perpendicular L89 L90
  perpendicular L92 L99
  perpendicular L91 L99
  perpendicular L98 L100
  horizontal L96
  coincident P138 P139
  perpendicular L92 L93
  coincident P136 L93
  coincident P136 L92
  coincident P133 L102
  perpendicular L102 L104
  perpendicular L104 L105
  perpendicular L109 L114
  perpendicular L113 L114
  perpendicular L107 L117
  horizontal L112
  coincident P155 P161
  perpendicular L109 L118
  coincident P159 L118
  coincident P159 L109
  coincident P158 L106
  perpendicular L106 L108
  perpendicular L108 L120
  coincident P181 P202
  coincident P201 P220
  dimension "d206" diameter = 6.5
  dimension "d232" angle L8 L9 = 120
  dimension "d233" distance P13 P14 = 6
  dimension "d237" diameter = 6.5
  dimension "d238" angle L21 L22 = 120
  dimension "d239" distance P33 P34 = 6
  dimension "d240" distance P30 P40 = 1
  dimension "d241" distance P28 P41 = 1
  dimension "d242" diameter = 6.5
  dimension "d243" angle L26 L28 = 120
  dimension "d244" distance P46 P48 = 6
  dimension "d245" distance P49 P61 = 1
  dimension "d246" distance P51 P54 = 1
  dimension "d247" diameter = 6.5
  dimension "d248" angle L39 L41 = 120
  dimension "d249" distance P67 P74 = 6
  dimension "d250" distance P72 P83 = 1
  dimension "d251" distance P75 P77 = 1
  dimension "d252" diameter = 6.5
  dimension "d253" angle L55 L57 = 120
  dimension "d254" distance P94 P98 = 6
  dimension "d255" distance P91 P105 = 1
  dimension "d256" distance P99 P101 = 1
  dimension "d257" diameter = 6.5
  dimension "d258" angle L75 L77 = 120
  dimension "d259" distance P115 P124 = 6
  dimension "d350" radius = 7
  dimension "d351" radius = 7
  dimension "d352" radius = 6.7
  dimension "d353" radius = 7
  dimension "d354" radius = 7
  dimension "d355" radius = 7
  dimension "d421" diameter = 6.5
  dimension "d422" angle L93 L96 = 120
  dimension "d423" distance P139 P146 = 6
  dimension "d424" radius = 7
  dimension "d425" distance P133 P153 = 2
  dimension "d426" diameter = 6.5
  dimension "d427" angle L112 L118 = 120
  dimension "d428" distance P155 P167 = 6
  dimension "d429" radius = 7
  dimension "d430" distance P154 P158 = 2
  dimension "d458" angle = 150
  dimension "d858" diameter = 6.5
  dimension "d859" angle = 120
  dimension "d860" distance P202 P203 = 6
  dimension "d861" diameter = 6.5
  dimension "d862" angle = 120
  dimension "d863" distance P208 P220 = 6
  dimension "d864" distance P210 P213 = 1
  dimension "d865" distance P214 P219 = 1
  dimension "d866" radius = 7
  dimension "d867" radius = 7
  dimension "d868" angle = 150
  dimension "d869" distance P197 P229 = 1
  dimension "d870" distance P186 P230 = 2
work_plane "WorkPlane6" sketch "Flipper" AlongDistance 11
sketch "Rubber Band Line" plane through (0, 0, 11) normal (0, 0, 1) x axis (1, 0, 0)
  line L1 (47.766, 7.9632) -> (0.9915, 12.4623)
  line L2 (0.1878, -12.5003) -> (47.7564, -7.9642)
  line L3 (47.766, 207.9632) -> (0.9915, 212.4623)
  line L4 (0.1878, 187.4997) -> (47.7564, 192.0358)
  arc A1 centre (0, 0) radius 12.5017 clockwise from (0.1878, -12.5003) to (0.9915, 12.4623)
  arc A2 centre (47, 0) radius 8 clockwise from (47.766, 7.9632) to (47.7564, -7.9642)
  arc A3 centre (47, 200) radius 8 clockwise from (47.766, 207.9632) to (47.7564, 192.0358)
  arc A4 centre (0, 200) radius 12.5017 clockwise from (0.1878, 187.4997) to (0.9915, 212.4623)
work_plane "WorkPlane7" PathDistance 0.8475
sketch "Rubber Band profile" plane through (23.6498, 10.2829, 13) normal (0.9954, -0.0957, 0) x axis (0.0957, 0.9954, 0)
  line L1 (-2.5, 5.1) -> (-2.5, -5.1)
  line L2 (2.5, -5.1) -> (2.5, 5.1)
  line L3 (2.5, 7.1) -> (-2.5, 5.1)
  line L4 (2.5, 7.1) -> (2.5, 5.1)
  line L5 (2.5, -7.1) -> (-2.5, -5.1)
  line L6 (2.5, -5.1) -> (2.5, -7.1)
  line L7 (2.5, 207.1) -> (2.5, 205.1)
  line L8 (-2.5, 205.1) -> (-2.5, 194.9)
  line L9 (2.5, 194.9) -> (2.5, 192.9)
  line L10 (2.5, 207.1) -> (-2.5, 205.1)
  line L11 (2.5, 192.9) -> (-2.5, 194.9)
  line L12 (2.5, 194.9) -> (2.5, 205.1)
  circle C1 centre (0, 0) radius 2
  circle C2 centre (0, 200) radius 2
  point P1 (0, 0)
  point P2 (0, 0)
  coincident P1 P2
sweep "Sweep1" sketch "Rubber Band profile" TwistAngle 0 TaperAngle 0
sketch "Silicon Chip Logo Flipper" plane through (0, 0, 25.7) normal (0, 0, 1) x axis (-1, 0, 0)
  line L1 (-47.7564, 7.9642) -> (0, 12.5)
  line L2 (-1.1968, -12.4426) -> (-47.766, -7.9632)
  curve K1
  curve K2
  curve K3
  curve K4
  line L3 (-47.7564, 7.9642) -> (0, 12.5)
  line L4 (-1.1968, -12.4426) -> (-47.766, -7.9632)
  arc A1 centre (0, 0) radius 12.5 clockwise from (0, 12.5) to (-1.1968, -12.4426)
  arc A2 centre (-47, 0) radius 8 clockwise from (-47.766, -7.9632) to (-47.7564, 7.9642)
  arc A3 centre (0, 0) radius 12.5 clockwise from (0, 12.5) to (-1.1968, -12.4426)
  arc A4 centre (-47, 0) radius 8 clockwise from (-47.766, -7.9632) to (-47.7564, 7.9642)
  dimension "d116" Text1-Height = 7
extrude "Extrude31" cut sketch "Flipper Drive Lower Assembly" profile of C2 C3 C4 C5 along normal blind 20
extrude "Extrude28" cut sketch "Silicon Chip Logo Flipper" against normal blind 0.6
sketch "37mm solenoid drill" plane through (0, 0, -46) normal (0, 0, -1) x axis (1, 0, 0)
  line L1 (-72.6464, -35.307) -> (-73.3163, -35.307)
  line L2 (-92.7503, -29.6387) -> (-60.4463, -11.5985)
  line L3 (-82.7298, -46.9948) -> (-92.7503, -29.6387)
  line L4 (-50.4258, -28.9545) -> (-82.7298, -46.9948)
  line L5 (-51.4186, -22.4904) -> (-55.4186, -15.5622)
  line L6 (-49.0676, -21.307) -> (-73.3163, -35.307)
  line L7 (-47.3633, -20.323) -> (-49.0676, -21.307)
  line L8 (-47.3633, -20.323) -> (-53.3977, -23.807)
  line L9 (-60.4463, -11.5985) -> (-53.3977, -23.807)
  line L10 (-39.3006, -23.807) -> (-53.3977, -23.807)
  line L11 (-50.4258, -28.9545) -> (-60.4463, -11.5985)
  line L12 (-92.7503, -29.6387) -> (-60.4463, -11.5985)
  line L13 (-44.7375, -18.807) -> (-49.0676, -21.307)
  circle C1 centre (-77.3163, -28.3788) radius 1.75
  circle C2 centre (-55.9958, -25.307) radius 1.75
  circle C3 centre (-59.9958, -18.3788) radius 1.75
  circle C4 centre (-73.3163, -35.307) radius 1.75
  circle C5 centre (-77.3163, -28.3788) radius 4
  circle C6 centre (-73.3163, -35.307) radius 4
  circle C7 centre (-59.9958, -18.3788) radius 4
  circle C8 centre (-55.9958, -25.307) radius 4
  point P7 (-73.3163, -35.307)
  point P12 (-73.3163, -35.307)
  point P13 (-49.0676, -21.307)
  point P17 (-60.4463, -11.5985)
  point P20 (-92.7503, -29.6387)
  point P25 (-44.7375, -18.807)
  parallel L2 L4
  coincident P7 P12
  perpendicular L5 L6
  horizontal L10
  parallel L9 L11
  parallel L2 L12
  concentric C1 C5
  concentric C4 C6
  concentric C3 C7
  concentric C2 C8
  perpendicular L5 L13
  dimension "d121" diameter C1 = 3.5
  dimension "d122" diameter C2 = 3.5
  dimension "d123" diameter C3 = 3.5
  dimension "d147" diameter C4 = 3.5
  dimension "d329" distance P12 P13 = 28
  dimension "d330" angle L9 L10 = 120
  dimension "d331" distance P17 P20 = 37
  dimension "d332" diameter C5 = 8
  dimension "d333" diameter C6 = 8
  dimension "d334" diameter C7 = 8
  dimension "d335" diameter C8 = 8
  dimension "d370" distance P13 P25 = 5
extrude "Extrude29" cut sketch "37mm solenoid drill" profile of C1 C2 C3 C4 L6 against normal blind 120
move "Move10" RotateAngle 180
sketch "22mm solenoid drill" plane through (0, 0, -45.2) normal (0, 0, -1) x axis (1, 0, 0)
  line L1 (-48.4737, -23.7852) -> (-73.4142, -23.7852)
  line L2 (-27.7707, -26.6775) -> (-54.4238, -26.6775)
  line L3 (-60.8568, -16.5352) -> (-60.4238, -16.2852)
  circle C1 centre (-37.9675, -17.1807) radius 1.8
  circle C2 centre (-56.9579, -14.2884) radius 1.8
  circle C3 centre (-73.4142, -23.7852) radius 1.75
  circle C4 centre (-54.4238, -26.6775) radius 1.75
  circle C5 centre (-54.4238, -26.6775) radius 4
  circle C6 centre (-73.4142, -23.7852) radius 4
  circle C7 centre (-60.4238, -16.2852) radius 1.75
  circle C8 centre (-60.4238, -16.2852) radius 4
  circle C9 centre (-67.4142, -34.1775) radius 1.75
  circle C10 centre (-67.4142, -34.1775) radius 4
  point P4 (-73.4142, -23.7852)
  point P8 (-73.4142, -23.7852)
  point P6 (-54.4238, -26.6775)
  point P10 (-54.4238, -26.6775)
  point P12 (-60.4238, -16.2852)
  point P16 (-60.4238, -16.2852)
  point P17 (-60.8568, -16.5352)
  horizontal L1
  coincident P4 P8
  horizontal L2
  coincident P6 P10
  coincident P12 P16
  dimension "d127" diameter C3 = 3.5
  dimension "d128" diameter C4 = 3.5
  dimension "d339" diameter C5 = 8
  dimension "d340" diameter C6 = 8
  dimension "d469" diameter C7 = 3.5
  dimension "d470" diameter C8 = 8
  dimension "d471" diameter C9 = 3.5
  dimension "d472" diameter C10 = 8
  dimension "d573" distance P16 P17 = 0.5
work_plane "WorkPlane8" sketch "Flipper Drive Perpendicular Plane" AlongDistance 20
sketch "Drive Hole Expansion Calcs" plane through (-11.4715, 16.383, 0) normal (-0.5736, 0.8192, 0) x axis (-0.8192, -0.5736, 0)
  line L1 (-20, -32.2) -> (-18, -32.2)
  line L2 (0, -34.2) -> (20.0402, -34.1996)
  line L3 (20, -30.2) -> (0, -30.2)
  line L4 (0, -34.2) -> (0, -34.2)
  line L5 (0, -30.2) -> (0, -30.2)
  arc A1 centre (20, -32.2) radius 2 clockwise from (20, -30.2) to (19.9599, -34.1996)
  circle C1 centre (10, -32.2) radius 2
  arc A2 centre (0, -32.2) radius 2 clockwise from (0, -34.2) to (0, -30.2)
  point P7 (20.0402, -34.1996)
  point P12 (19.9599, -34.1996)
  point P14 (0, -30.2)
  point P15 (0, -34.2)
  coincident P7 A1
  tangent L2 A2
  tangent L3 A1
  horizontal L4
  parallel L1 L5
  coincident L2 P12
  coincident A2 P14
  coincident A2 P15
  dimension "d171" diameter A2 = 4
  dimension "d172" diameter A1 = 4
  dimension "d174" diameter C1 = 4
extrude "Extrude30" cut sketch "22mm solenoid drill" profile of C3 C4 against normal blind 50
extrude "Extrude33" add sketch "Flipper Drive Top Labelling" profile of C1 C2 along normal blind 1
extrude "Extrude34" add sketch "Flipper Drive Top Labelling" profile of C2 C3 along normal blind 7.7
sketch "Solenoid Drive Washer" plane through (0, 0, -21.4) normal (0, 0, -1) x axis (1, 0, 0)
  line L1 (-20.2309, -4.9709) -> (-24.4204, 2.2855)
  line L2 (-6.7129, -2.3124) -> (-0.123, 7.0989)
  line L3 (6.7129, 2.3124) -> (0.123, -7.0989)
  arc A1 centre (-5, 8.6603) radius 6 clockwise from (-10.8144, 10.1409) to (-6.625, 2.8845)
  circle C1 centre (-5, 8.6603) radius 6
  circle C2 centre (-5, 8.6603) radius 1.75
  arc A2 centre (0, 0) radius 7.1 clockwise from (-0.123, 7.0989) to (6.7129, 2.3124)
  arc A3 centre (0, 0) radius 7.1 clockwise from (0.123, -7.0989) to (-6.7129, -2.3124)
  circle C3 centre (0, 0) radius 15
  circle C4 centre (-5, 208.6603) radius 1.75
  circle C5 centre (-5, 208.6603) radius 6
extrude "Extrude36" new body sketch "Solenoid Drive Washer" profile of A1 C1 C2 blind 1 from offset 0.2 bodies "Drive Arm Washer"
